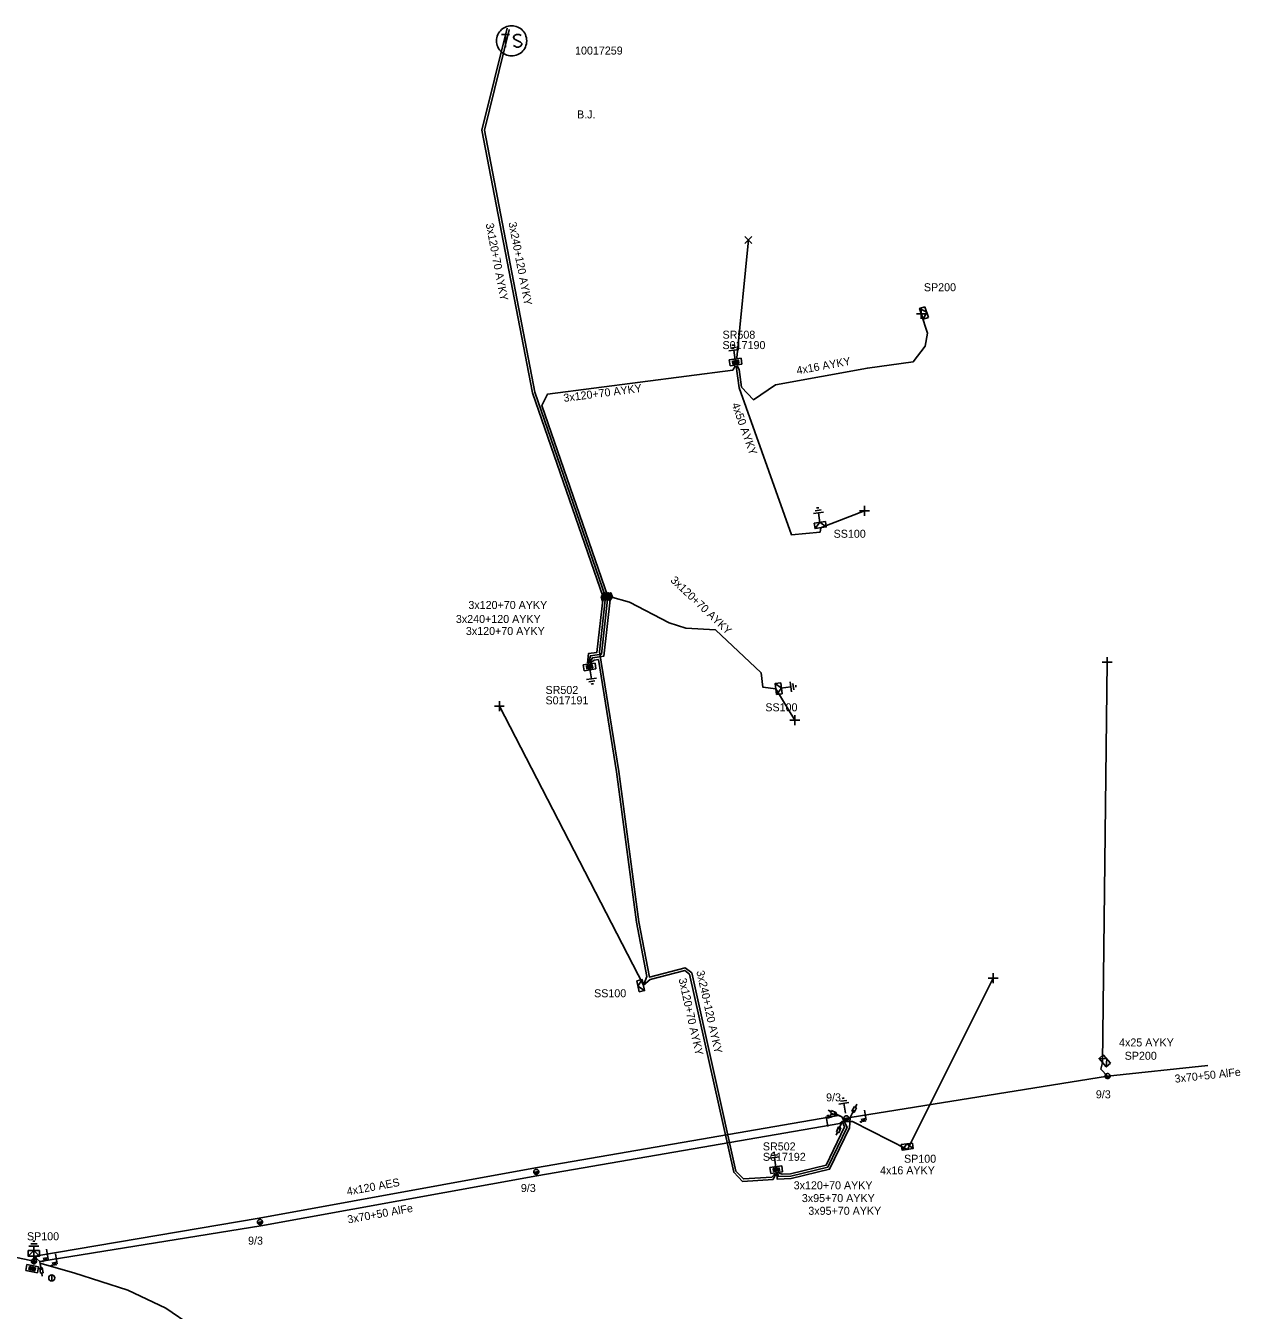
# Model space of a CAD drawing. Extents: x -717562 to -713845, y -1151196 to -1143903.
# Drawn here: x -714924.8 to -714773, y -1150297.7 to -1150137.1 of the extents above; entities that cross this region are included whole.
import ezdxf

# ---------------------------------------------------------------- set-up
doc = ezdxf.new("R2010")
doc.units = 0
for name, color, linetype in [('Vrstva 1', 7, 'Continuous'), ('Vrstva 10', 7, 'Continuous'), ('Vrstva 12', 7, 'Continuous'), ('Vrstva 13', 7, 'Continuous'), ('Vrstva 14', 7, 'Continuous'), ('Vrstva 15', 7, 'Continuous'), ('Vrstva 16', 7, 'Continuous'), ('Vrstva 18', 7, 'Continuous'), ('Vrstva 19', 7, 'Continuous'), ('Vrstva 2', 7, 'Continuous'), ('Vrstva 25', 7, 'Continuous'), ('Vrstva 26', 7, 'Continuous'), ('Vrstva 27', 7, 'Continuous'), ('Vrstva 28', 7, 'Continuous'), ('Vrstva 29', 7, 'Continuous'), ('Vrstva 30', 7, 'Continuous'), ('Vrstva 31', 7, 'Continuous'), ('Vrstva 33', 7, 'Continuous'), ('Vrstva 34', 7, 'Continuous'), ('Vrstva 36', 7, 'Continuous'), ('Vrstva 4', 7, 'Continuous'), ('Vrstva 5', 7, 'Continuous'), ('Vrstva 50', 7, 'Continuous'), ('Vrstva 51', 7, 'Continuous'), ('Vrstva 52', 7, 'Continuous'), ('Vrstva 54', 7, 'Continuous'), ('Vrstva 59', 7, 'Continuous'), ('Vrstva 6', 7, 'Continuous'), ('Vrstva 8', 7, 'Continuous'), ('Vrstva 9', 7, 'Continuous')]:
    doc.layers.add(name, color=color, linetype=linetype)

# ---------------------------------------------------------------- blocks, each defined once
blk = doc.blocks.new('NN440')
at = {"layer": 'Vrstva 2'}
for points in [[(0.63, 0), (0.63, 0.06), (0.62, 0.13), (0.6, 0.19), (0.58, 0.25), (0.55, 0.31), (0.51, 0.37), (0.47, 0.42), (0.42, 0.46), (0.37, 0.51), (0.32, 0.54), (0.26, 0.57), (0.2, 0.59), (0.13, 0.61), (0.07, 0.62), (0, 0.63), (-0.06, 0.62), (-0.13, 0.61), (-0.19, 0.59), (-0.26, 0.57), (-0.31, 0.54), (-0.37, 0.51), (-0.42, 0.46), (-0.47, 0.42), (-0.51, 0.37), (-0.54, 0.31), (-0.57, 0.25), (-0.6, 0.19), (-0.62, 0.13), (-0.63, 0.06), (-0.63, 0), (-0.63, -0.07), (-0.62, -0.14), (-0.6, -0.2), (-0.57, -0.26), (-0.54, -0.32), (-0.51, -0.37), (-0.47, -0.43), (-0.42, -0.47), (-0.37, -0.51), (-0.31, -0.55), (-0.26, -0.58), (-0.19, -0.6), (-0.13, -0.62), (-0.06, -0.63), (0, -0.63), (0.07, -0.63), (0.13, -0.62), (0.2, -0.6), (0.26, -0.58), (0.32, -0.55), (0.37, -0.51), (0.42, -0.47), (0.47, -0.43), (0.51, -0.37), (0.55, -0.32), (0.58, -0.26), (0.6, -0.2), (0.62, -0.14), (0.63, -0.07), (0.63, 0)], [(-0.63, 0), (0.63, 0)], [(-0.6, -0.18), (0.57, -0.18)], [(-0.51, -0.32), (0.5, -0.32)], [(-0.37, -0.47), (0.35, -0.47)]]:
    blk.add_lwpolyline(points, dxfattribs=at)
blk = doc.blocks.new('NN840')
at = {"layer": 'Vrstva 15'}
for points in [[(0, 0.62), (0, -0.63)], [(-0.75, -0.71), (-0.75, -0.66)], [(-0.73, -0.76), (-0.75, -0.71)], [(-0.66, -0.8), (-0.73, -0.76)], [(-0.63, -0.8), (-0.66, -0.8)], [(-0.56, -0.76), (-0.63, -0.8)], [(-0.54, -0.71), (-0.56, -0.76)], [(-0.54, -0.38), (-0.54, -0.71)], [(-0.33, -0.38), (-0.33, -0.8)], [(-0.33, -0.64), (-0.13, -0.38)], [(-0.26, -0.56), (-0.09, -0.8)]]:
    blk.add_lwpolyline(points, dxfattribs=at)
blk = doc.blocks.new('NN770')
at = {"layer": 'Vrstva 10'}
for p, q in [((0, 0.19), (0, 0.26)), ((0, -0.28), (0, 0.11))]:
    blk.add_line(p, q, dxfattribs=at)
blk.add_circle((0, -0.01), 0.375, dxfattribs=at)
blk = doc.blocks.new('NN870')
at = {"layer": 'Vrstva 4'}
for points in [[(0, -0.25), (0.5, 0), (0, 0.25), (-0.5, 0), (0, -0.25)], [(0.37, 0), (0, 0.19), (-0.36, 0), (0, -0.19), (0.37, 0)], [(0.24, 0), (0, 0.12), (-0.25, 0), (0, -0.12), (0.24, 0)], [(0.12, 0), (0, 0.06), (-0.13, 0), (0, -0.06), (0.12, 0)]]:
    blk.add_lwpolyline(points, dxfattribs=at)
blk = doc.blocks.new('NN800')
at = {"layer": 'Vrstva 1'}
for points in [[(-0.44, 0.44), (0.44, -0.44)], [(-0.44, -0.44), (0.44, 0.44)]]:
    blk.add_lwpolyline(points, dxfattribs=at)
blk = doc.blocks.new('NN820')
at = {"layer": 'Vrstva 13'}
for points in [[(0, 0), (0, -1.05)], [(-0.16, -0.81), (0.16, -0.81)], [(-0.16, -1.47), (-0.16, -0.81)], [(0.16, -1.47), (-0.16, -1.47)], [(0, -1.05), (-0.06, -0.93)], [(0, -1.05), (0.06, -0.93)], [(0, -1.47), (0, -1.87)], [(0.16, -0.81), (0.16, -1.47)]]:
    blk.add_lwpolyline(points, dxfattribs=at)
blk = doc.blocks.new('NN620')
at = {"layer": 'Vrstva 8'}
for points in [[(0.75, 0), (-0.75, 0)], [(-0.75, 0), (-0.75, -0.75)], [(0.75, -0.75), (0.75, 0)], [(-0.75, -0.75), (0.75, -0.75)], [(0.37, -0.18), (-0.38, -0.18)], [(-0.38, -0.18), (-0.38, -0.56)], [(-0.38, -0.56), (0.37, -0.56)], [(0.32, -0.23), (-0.33, -0.23)], [(-0.33, -0.23), (-0.33, -0.51)], [(-0.33, -0.51), (0.32, -0.51)], [(0.27, -0.27), (-0.28, -0.27)], [(-0.28, -0.27), (-0.28, -0.46)], [(-0.28, -0.46), (0.27, -0.46)], [(0.23, -0.32), (-0.23, -0.32)], [(-0.23, -0.32), (-0.23, -0.42)], [(-0.23, -0.42), (0.23, -0.42)], [(-0.19, -0.37), (0.19, -0.37)], [(0.23, -0.42), (0.23, -0.32)], [(0.27, -0.46), (0.27, -0.27)], [(0.32, -0.51), (0.32, -0.23)], [(0.37, -0.56), (0.37, -0.18)]]:
    blk.add_lwpolyline(points, dxfattribs=at)
blk = doc.blocks.new('NN630')
at = {"layer": 'Vrstva 9'}
for points in [[(0, -0.7), (-0.7, 0)], [(-0.7, -0.7), (-0.7, 0), (0.7, 0), (0.7, -0.7)], [(-0.7, -0.7), (0.7, -0.7)], [(0, -0.7), (0.7, 0)]]:
    blk.add_lwpolyline(points, dxfattribs=at)
blk = doc.blocks.new('NN810')
at = {"layer": 'Vrstva 14'}
for points in [[(0, -0.64), (0, -1.89)], [(0.63, -1.89), (-0.62, -1.89)], [(0.39, -2.2), (-0.4, -2.2)], [(0, -2.52), (-0.12, -2.52)], [(0.14, -2.52), (0, -2.52)]]:
    blk.add_lwpolyline(points, dxfattribs=at)
blk = doc.blocks.new('NN610')
at = {"layer": 'Vrstva 6'}
for points in [[(1.88, 0), (1.87, 0.2), (1.84, 0.39), (1.79, 0.58), (1.72, 0.77), (1.63, 0.94), (1.52, 1.11), (1.4, 1.26), (1.26, 1.4), (1.1, 1.53), (0.94, 1.63), (0.76, 1.72), (0.58, 1.8), (0.19, 1.88), (0.19, 1.88), (-0.01, 1.89), (-0.21, 1.88), (-0.4, 1.85), (-0.59, 1.8), (-0.78, 1.72), (-0.95, 1.63), (-1.12, 1.53), (-1.27, 1.4), (-1.41, 1.26), (-1.54, 1.11), (-1.64, 0.94), (-1.73, 0.77), (-1.8, 0.58), (-1.86, 0.39), (-1.89, 0.2), (-1.9, 0), (-1.89, -0.2), (-1.86, -0.39), (-1.8, -0.58), (-1.73, -0.77), (-1.64, -0.95), (-1.54, -1.11), (-1.41, -1.27), (-1.27, -1.41), (-1.12, -1.53), (-0.95, -1.64), (-0.78, -1.73), (-0.59, -1.8), (-0.4, -1.85), (-0.21, -1.88), (-0.01, -1.89), (0.19, -1.88), (0.39, -1.85), (0.58, -1.8), (0.76, -1.73), (0.94, -1.64), (1.1, -1.53), (1.26, -1.41), (1.4, -1.27), (1.52, -1.11), (1.63, -0.95), (1.72, -0.77), (1.79, -0.58), (1.84, -0.39), (1.87, -0.2), (1.88, 0)], [(-1.27, 0.78), (-0.26, 0.78)], [(-0.76, 0.78), (-0.76, -0.79)], [(1.19, 0.66), (0.94, 0.78), (0.62, 0.78), (0.37, 0.66), (0.24, 0.47), (0.24, 0.4), (0.37, 0.22), (1.12, -0.16), (1.25, -0.32), (1.25, -0.48), (1.12, -0.67), (0.87, -0.79), (0.62, -0.79), (0.49, -0.73), (0.24, -0.6)]]:
    blk.add_lwpolyline(points, dxfattribs=at)

msp = doc.modelspace()

# ---------------------------------------------------------------- linework, layer by layer
at = {"layer": 'Vrstva 1'}
for points in [[(-715091.6, -1150261.12), (-715058.41, -1150262.48), (-715024.51, -1150268.38), (-714989.1, -1150278.29), (-714956.7, -1150284.53), (-714923.79, -1150291.53)], [(-714777.11, -1150267.04), (-714789.63, -1150268.38), (-714821.8, -1150273.57)], [(-714822.79, -1150274.05), (-714823.1, -1150274.3), (-714860.93, -1150280.84), (-714895.45, -1150287.11), (-714923.04, -1150291.55)]]:
    msp.add_lwpolyline(points, dxfattribs=at)
at = {"layer": 'Vrstva 5'}
for points in [[(-714854.62, -1150216.78), (-714854.51, -1150215.58), (-714853.43, -1150215.42), (-714852.67, -1150208.51), (-714861.5, -1150182.97), (-714867.8, -1150150.16), (-714864.67, -1150137.39)], [(-714831.22, -1150280.6), (-714831.56, -1150281.02), (-714835.14, -1150281.24), (-714836.06, -1150280.26), (-714841.58, -1150255.49), (-714842.4, -1150254.85), (-714846.87, -1150256), (-714848.19, -1150249.1), (-714850.68, -1150230.3), (-714853.12, -1150215.34), (-714852.36, -1150208.48), (-714861.21, -1150182.89), (-714867.49, -1150150.16), (-714864.42, -1150137.61), (-714864.4, -1150137.56)], [(-714854.49, -1150216.76), (-714854.24, -1150215.85), (-714852.85, -1150215.64), (-714852.06, -1150208.44), (-714860.31, -1150184.59), (-714859.6, -1150183.14), (-714836.46, -1150180.16), (-714836.17, -1150179.66)], [(-714854.24, -1150216.72), (-714853.77, -1150216.38), (-714853.26, -1150216.33), (-714850.98, -1150230.34), (-714848.49, -1150249.15), (-714847.19, -1150255.94), (-714847.63, -1150257.01), (-714846.8, -1150256.29), (-714842.47, -1150255.18), (-714841.85, -1150255.66), (-714836.33, -1150280.41), (-714835.26, -1150281.55), (-714831.43, -1150281.31), (-714831.09, -1150280.59)], [(-714821.8, -1150273.57), (-714821.87, -1150274.83), (-714824.36, -1150280.02), (-714829.18, -1150281.19), (-714830.93, -1150281.26), (-714830.96, -1150280.57)], [(-714822.85, -1150273.46), (-714822.18, -1150274.77), (-714824.57, -1150279.76), (-714829.22, -1150280.89), (-714830.74, -1150280.95), (-714830.83, -1150280.55)], [(-714822.79, -1150274.05), (-714822.48, -1150274.72), (-714824.78, -1150279.5), (-714829.26, -1150280.59), (-714830.29, -1150280.63), (-714830.7, -1150280.53)], [(-714868.14, -1150330.54), (-714868.18, -1150331.09), (-714871.39, -1150330.89), (-714874.42, -1150330.07), (-714876.67, -1150328.74), (-714880.02, -1150326.23), (-714886.1, -1150319.88), (-714895.94, -1150309.07), (-714896.09, -1150307.48), (-714900.21, -1150303.54), (-714904, -1150299.64), (-714907.29, -1150297.39), (-714912.07, -1150295.14), (-714918.82, -1150292.96), (-714923.04, -1150291.75)]]:
    msp.add_lwpolyline(points, dxfattribs=at)
at = {"layer": 'Vrstva 50'}
msp.add_lwpolyline([(-714822.85, -1150273.46), (-714823.27, -1150273.31), (-714861.11, -1150279.86), (-714895.63, -1150286.13), (-714923.44, -1150290.86), (-714923.79, -1150291.53)], dxfattribs=at)
at = {"layer": 'Vrstva 52'}
for points in [[(-714835.91, -1150179.62), (-714835.68, -1150180.06), (-714835.37, -1150182.29), (-714833.86, -1150183.85), (-714831.11, -1150181.99), (-714819.63, -1150179.9), (-714813.9, -1150179.11), (-714812.43, -1150177.17), (-714812.12, -1150175.52), (-714812.9, -1150173.1)], [(-714836.04, -1150179.64), (-714835.66, -1150182.36), (-714829.11, -1150200.74), (-714825.55, -1150200.4), (-714825.47, -1150199.85)], [(-714854.37, -1150216.74), (-714854, -1150216.11), (-714852.58, -1150215.9), (-714851.76, -1150208.47), (-714849.37, -1150209.17), (-714844.39, -1150211.75), (-714842.34, -1150212.38), (-714838.63, -1150212.6), (-714832.92, -1150218), (-714832.69, -1150219.79), (-714831.09, -1150219.99)], [(-714789.63, -1150268.38), (-714790.45, -1150267.53), (-714790.25, -1150266.7)], [(-714822.79, -1150274.05), (-714821.49, -1150274.07), (-714814.62, -1150277.54)], [(-714923.04, -1150291.55), (-714923.8, -1150290.9)]]:
    msp.add_lwpolyline(points, dxfattribs=at)
at = {"layer": 'Vrstva 59'}
for points in [[(-714835.97, -1150178.61), (-714834.5, -1150163.88)], [(-714825.48, -1150199.85), (-714820, -1150197.75)], [(-714790.24, -1150266.7), (-714789.69, -1150216.63)], [(-714831.09, -1150219.99), (-714828.69, -1150223.88)], [(-714847.63, -1150257.01), (-714865.63, -1150222.13)], [(-714814.62, -1150277.54), (-714803.94, -1150256.13)]]:
    msp.add_lwpolyline(points, dxfattribs=at)

# ---------------------------------------------------------------- block references
at = {"layer": 'Vrstva 13'}
for p, xscale, yscale, rotation in [((-714789.63, -1150268.38), 0.5000000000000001, 0.5000000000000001, 9.168966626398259), ((-714822.28, -1150273.65), 0.5000000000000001, 0.5, 9.16896661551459), ((-714861.02, -1150280.35), 0.5, 0.5, 10.294622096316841), ((-714895.54, -1150286.62), 0.5, 0.5, 10.294622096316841), ((-714923.79, -1150291.53), 0.49999999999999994, 0.5000000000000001, -10.409872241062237)]:
    msp.add_blockref('NN440', p, dxfattribs=dict(at, xscale=xscale, yscale=yscale, rotation=rotation))
at = {"layer": 'Vrstva 15'}
for p, rotation in [((-714836.06, -1150179.52), -171.67175002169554), ((-714825.47, -1150199.85), -171.53871118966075), ((-714854.41, -1150216.87), 8.846652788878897), ((-714831.08, -1150219.99), 97.76516663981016), ((-714822.28, -1150273.65), -171.20722919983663), ((-714830.98, -1150280.44), -172.0571027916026), ((-714923.79, -1150291.53), 180)]:
    msp.add_blockref('NN810', p, dxfattribs=dict(at, rotation=rotation))
at = {"layer": 'Vrstva 16'}
for p, rotation in [((-714822.85, -1150273.46), -115.36889169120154), ((-714821.8, -1150273.57), 152.688952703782), ((-714822.79, -1150274.05), -23.087786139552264), ((-714923.04, -1150291.55), 9.136358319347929)]:
    msp.add_blockref('NN820', p, dxfattribs=dict(at, rotation=rotation))
at = {"layer": 'Vrstva 18'}
for p, rotation in [((-714819.89, -1150273.26), 9.168966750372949), ((-714824.67, -1150274.06), -170.1878805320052), ((-714922.12, -1150290.64), 10.294622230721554), ((-714920.98, -1150291.22), 9.1523888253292)]:
    msp.add_blockref('NN840', p, dxfattribs=dict(at, rotation=rotation))
at = {"layer": 'Vrstva 19'}
for p, rotation in [((-714852.67, -1150208.51), -96.26071108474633), ((-714852.36, -1150208.47), -96.26071109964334), ((-714852.06, -1150208.44), -96.26071109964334), ((-714851.76, -1150208.47), 83.74080557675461)]:
    msp.add_blockref('NN870', p, dxfattribs=dict(at, rotation=rotation))
at = {"layer": 'Vrstva 25'}
msp.add_blockref('NN610', (-714864.09, -1150138.99), dxfattribs=at)
at = {"layer": 'Vrstva 28'}
for p, rotation in [((-714836.06, -1150179.51), -171.67175002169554), ((-714854.41, -1150216.87), 8.846652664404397), ((-714830.98, -1150280.44), -172.0571027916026), ((-714924.08, -1150292.82), 168.715988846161)]:
    msp.add_blockref('NN620', p, dxfattribs=dict(at, rotation=rotation))
at = {"layer": 'Vrstva 31'}
for p, rotation in [((-714812.9, -1150173.1), 107.51951393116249), ((-714825.48, -1150199.85), -171.53871118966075), ((-714831.08, -1150219.99), 96.88172497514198), ((-714847.63, -1150257.01), -77.69553892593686), ((-714790.24, -1150266.7), 130.5391527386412), ((-714814.62, -1150277.54), -172.0571027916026), ((-714923.8, -1150290.9), 180)]:
    msp.add_blockref('NN630', p, dxfattribs=dict(at, rotation=rotation))
at = {"layer": 'Vrstva 34'}
msp.add_blockref('NN800', (-714834.5, -1150163.88), dxfattribs=at)
for p, rotation in [((-714812.9, -1150173.1), 45), ((-714820, -1150197.75), 45), ((-714789.69, -1150216.63), 44.99999995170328), ((-714865.63, -1150222.13), 45), ((-714828.69, -1150223.88), 44.99999995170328), ((-714803.94, -1150256.13), 44.99999995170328), ((-714923.8, -1150290.9), 45)]:
    msp.add_blockref('NN800', p, dxfattribs=dict(at, rotation=rotation))
at = {"layer": 'Vrstva 36'}
msp.add_blockref('NN770', (-714921.56, -1150293.6), dxfattribs=at)

# ---------------------------------------------------------------- texts
at = {"layer": 'Vrstva 12'}
for p in [(-714824.8, -1150271.54), (-714791.09, -1150271.16), (-714862.94, -1150282.87), (-714897.03, -1150289.45)]:
    msp.add_text('9/3', height=1, dxfattribs=at).set_placement(p)
at = {"layer": 'Vrstva 2'}
for rotation, p in [(6.17, (-714781.19, -1150269.22)), (10.295, (-714884.52, -1150286.81))]:
    msp.add_text('3x70+50 AlFe', height=1, rotation=rotation, dxfattribs=at).set_placement(p)
at = {"layer": 'Vrstva 26'}
msp.add_text('10017259', height=1, dxfattribs=at).set_placement((-714856.17, -1150140.71))
at = {"layer": 'Vrstva 27'}
msp.add_text('B.J.', height=1, dxfattribs=at).set_placement((-714855.92, -1150148.69))
at = {"layer": 'Vrstva 29'}
for s, p in [('S017190', (-714837.74, -1150177.52)), ('S017191', (-714859.86, -1150221.92)), ('S017192', (-714832.7, -1150278.97))]:
    msp.add_text(s, height=1, dxfattribs=at).set_placement(p)
at = {"layer": 'Vrstva 30'}
for s, p in [('SR508', (-714837.74, -1150176.22)), ('SR502', (-714859.86, -1150220.62)), ('SR502', (-714832.7, -1150277.67))]:
    msp.add_text(s, height=1, dxfattribs=at).set_placement(p)
at = {"layer": 'Vrstva 33'}
for s, p in [('SP200', (-714812.58, -1150170.29)), ('SS100', (-714823.86, -1150201.1)), ('SS100', (-714832.39, -1150222.79)), ('SS100', (-714853.79, -1150258.53)), ('SP200', (-714787.49, -1150266.34)), ('SP100', (-714815.06, -1150279.21)), ('SP100', (-714924.66, -1150288.9))]:
    msp.add_text(s, height=1, dxfattribs=at).set_placement(p)
at = {"layer": 'Vrstva 51'}
msp.add_text('4x120 AES', height=1, rotation=10.294, dxfattribs=at).set_placement((-714884.61, -1150283.3))
at = {"layer": 'Vrstva 54'}
for s, rotation, p in [('4x16 AYKY', 10.318, (-714828.4, -1150180.7)), ('4x50 AYKY', 289.601, (-714836.62, -1150184.42)), ('3x120+70 AYKY', 316.598, (-714844.32, -1150206.51))]:
    msp.add_text(s, height=1, rotation=rotation, dxfattribs=at).set_placement(p)
for s, p in [('4x25 AYKY', (-714788.19, -1150264.68)), ('4x16 AYKY', (-714818.05, -1150280.66))]:
    msp.add_text(s, height=1, dxfattribs=at).set_placement(p)
at = {"layer": 'Vrstva 6'}
for s, rotation, p in [('3x120+70 AYKY', 280.868, (-714867.34, -1150161.87)), ('3x240+120 AYKY', 280.867, (-714864.49, -1150161.72)), ('3x120+70 AYKY', 7.362, (-714857.55, -1150184.13)), ('3x120+70 AYKY', 282.562, (-714843.24, -1150256.25)), ('3x240+120 AYKY', 282.563, (-714841.02, -1150255.29))]:
    msp.add_text(s, height=1, rotation=rotation, dxfattribs=at).set_placement(p)
for s, p in [('3x120+70 AYKY', (-714869.5, -1150210)), ('3x240+120 AYKY', (-714871.06, -1150211.75)), ('3x120+70 AYKY', (-714869.81, -1150213.25)), ('3x120+70 AYKY', (-714828.85, -1150282.53)), ('3x95+70 AYKY', (-714827.83, -1150284.13)), ('3x95+70 AYKY', (-714827.02, -1150285.72))]:
    msp.add_text(s, height=1, dxfattribs=at).set_placement(p)

doc.saveas('drawing.dxf')
